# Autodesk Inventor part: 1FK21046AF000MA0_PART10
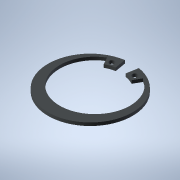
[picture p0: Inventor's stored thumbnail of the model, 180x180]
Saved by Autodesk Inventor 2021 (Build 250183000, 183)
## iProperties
Created: 2025-04
Part Number: 1FK21046AF000MA0_PART10
Material: Generic
Catalog Web Link: www.3dfindit.com
Description: -Servo synchronous motor
Document SubType Name: Modeling
Designer: psAdmin
Mass: 0.642463 g
Surface Area: 12.3927 cm^2
Volume: 0.642463 cm^3
Density: 1 g/cm^3
Appearance: PSOLRGB-212-217-219
Category: PARTsolutions
Title: 1FK21046AF000MA0_PART10
Author: Cadenas PARTsolutions
Comments: Servo synchronous motor
Sending System: PARTsolutions
Preprocessor: ST-DEVELOPER v19.3
PSOL_IDENT_0: {$CADENAS_DATA/23d-libs/siemens_ag/_cat_/1c/1f/1fk21046af000ma0.prj},216 {VTYP=3D},{NB=1FK21046AF000
PSOL_IDENT_1: MA0_PART10},{LINA=1FK21046AF000MA0_PART10},{NN=1FK21046AF000MA0_PART10},{NOPRJ=TRUE},{DATE=19.08.202
PSOL_IDENT_2: 5 14:00:28},{GEOMDATE=30.07.2025 02:02:08},{VERSION=},{LINEID=10},{WBVAR=},{WBNUMERIC=}  {NB=1FK2104
PSOL_IDENT_3: 6AF000MA0_PART10},{LINA=1FK21046AF000MA0_PART10},{KT=DUMMY},{PREVIEW=../../../_pool_/cb/72/p_d211_xx
PSOL_IDENT_4: _00434j.png},{DESCSHORT=SIMOTICS S-1FK2 HD, SINAMICS S210 3AC 400V-480V, 3.2 Nm, 3000 rpm},{DESCLONG=
PSOL_IDENT_5: SIMOTICS S-1FK2 HD servo motor M0=3.2 Nm; PN = 1 kW at nN=3000 rpm (380-480 V); PN = 0.5 kW at nN=15
PSOL_IDENT_6: 00 rpm (200-240 V); degree of protection IP64; cylindrical shaft D19x40mm; absolute encoder 22-bit +
PSOL_IDENT_7: 12-bit multiturn (encoder AM22DQC); with OCC interface; plug size M17, rotatable; SIMOTICS S-1FK2 s
PSOL_IDENT_8: ervomotorfor a wide range of uses in industrial environments. SIMOTICS S‑1FK2 servomotors are compac
PSOL_IDENT_9: t synchronous motors with a high dynamic performance that set themselves apart as a result of their
PSOL_IDENT_10: high power density, degree of protection and overload capability. The motors are available in two va
PSOL_IDENT_11: riants: as High Dynamic variant (highest dynamic performance as a result of the low intrinsic moment
PSOL_IDENT_12: of inertia for applications demanding a high dynamic performance with low moved masses) - and as Co
PSOL_IDENT_13: mpact variant (precise and stable closed-loop control for medium up to large moved masses as a resul
PSOL_IDENT_14: t of a medium intrinsic moment of inertia). SIMOTICSS‑1FK2 servomotors fully exploit their strengths
PSOL_IDENT_15: in a system with the SINAMICSS210 frequency converter and simple connection using the one cable con
PSOL_IDENT_16: nection (OCC). Advantages include the short control and positioning times, fast and precise correcti
PSOL_IDENT_17: on of disturbing quantities as well as stable control with a high dynamic performance. The servo mot
PSOL_IDENT_18: ors can be configured to address a wide range of requirements. For example with and without holding
PSOL_IDENT_19: brake, IP64 or IP65 degree of protection, singleturn or multiturn absolute encoders - to name just a
PSOL_IDENT_20: few. Further, the servomotors are available in different shaft heights extending from 20 to 100. A
PSOL_IDENT_21: shaft sealing ring is available to achieve an IP65 degree of protection and for subsequent mounting
PSOL_IDENT_22: at the motor or as spare part. SIMOTICS - the optimum motor for each and every motion control applic
PSOL_IDENT_23: ation.},{INTNO=195125049666},{SUPPLIERALTNO=1FK2104-6AF00-0MA0},{MANUID=1FK21046AF000MA0},{MANUNAME=
PSOL_IDENT_24: Siemens},{MANUTYPEDESC=Synchronous motor 1FK2-HD 3.2 NM},{AAU732=SIMOTICS},{AAO057=S-1FK2},{AAU734=S
PSOL_IDENT_25: IMOTICS S-1FK2 HD servo motor M0=3.2 Nm; PN = 1 kW at nN=3000 rpm (380-480 V); PN = 0.5 kW at nN=150
PSOL_IDENT_26: 0 rpm (200-240 V); degree of protection IP64; cylindrical shaft D19x40mm; absolute encoder 22-bit +
PSOL_IDENT_27: 12-bit multiturn (encoder AM22DQC); with OCC interface; plug size M17, rotatable;},{AAW338=Synchrono
PSOL_IDENT_28: us motor 1FK2-HD 3.2 NM},{AAO742=SIMOTICS},{AAO663=4042948694374},{NOCUPEROU=1},{PRICEQUANTITY=1},{Q
PSOL_IDENT_29: UANTITYMIN=1},{QUANTITYINT=1},{CTN=85015220},{COO=DE},{AAO676=1FK2104-6AF00-0MA0},{AAO677=Siemens AG
PSOL_IDENT_30: },{ORDERUNIT=C62},{CONTENTUNIT=C62}
NB: 1FK21046AF000MA0_PART10
NT: Servo synchronous motor
NBSYN: $MANUID._PART10
LINA: 1FK21046AF000MA0_PART10
CATALOG: SIEMENS
PREVIEW: ../../../_pool_/cb/72/p_d211_xx_00434j.png
DESCSHORT: SIMOTICS S-1FK2 HD, SINAMICS S210 3AC 400V-480V, 3.2 Nm, 3000 rpm
DESCLONG: SIMOTICS S-1FK2 HD servo motor M0=3.2 Nm; PN = 1 kW at nN=3000 rpm (380-480 V); PN = 0.5 kW at nN=1500 rpm (200-240 V); degree of protection IP64; cylindrical s
INTNO: 195125049666
SUPPLIERALTNO: 1FK2104-6AF00-0MA0
MANUID: 1FK21046AF000MA0
MANUNAME: Siemens
MANUTYPEDESC: Synchronous motor 1FK2-HD 3.2 NM
AAU732: SIMOTICS
AAO057: S-1FK2
AAU734: SIMOTICS S-1FK2 HD servo motor M0=3.2 Nm; PN = 1 kW at nN=3000 rpm (380-480 V); PN = 0.5 kW at nN=1500 rpm (200-240 V); degree of protection IP64; cylindrical s
AAW338: Synchronous motor 1FK2-HD 3.2 NM
AAO742: SIMOTICS
AAO663: 4042948694374.0
NOCUPEROU: 1
PRICEQUANTITY: 1
QUANTITYMIN: 1
QUANTITYINT: 1
CTN: 85015220
COO: DE
ARTICLENO: 1FK21046AF000MA0_PART10
BOMINFO: 1FK21046AF000MA0_PART10
CREATOR: CADENAS GmbH
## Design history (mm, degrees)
feature "2025_04_17_15_39_11_0412"
body "Solid1"
